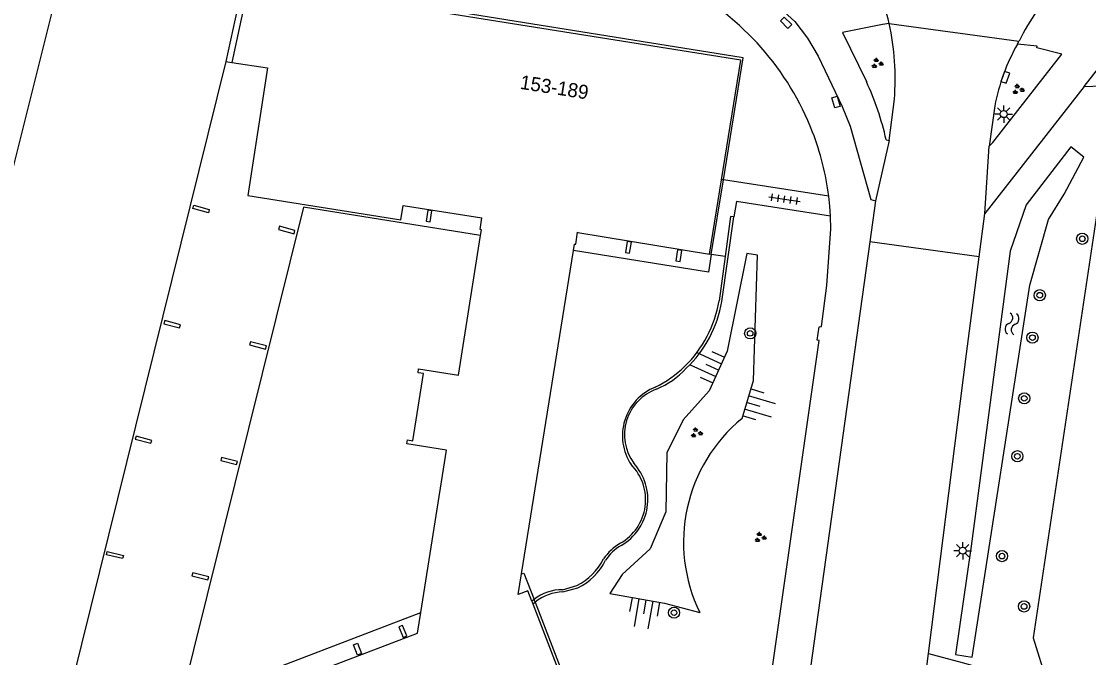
# Model space of a CAD drawing. Extents: x 131000 to 133013, y 393000 to 396501.
# Drawn here: x 131578.2 to 131654.4, y 394722.3 to 394767.7 of the extents above; entities that cross this region are included whole.
import ezdxf

# ---------------------------------------------------------------- set-up
doc = ezdxf.new("R2010")
doc.units = 0
for name, color, linetype in [('gg-afsc-hekwerk', 7, 'Continuous'), ('gg-afsc-muur', 7, 'Continuous'), ('gg-anno-huisnummerreeks BGT', 7, 'Continuous'), ('gg-bbg-hoofdgebouw', 7, 'Continuous'), ('gg-bbg-luifel en loopbrug', 7, 'Continuous'), ('gg-bbg-onder overbouw', 7, 'Continuous'), ('gg-bbg-pand overbouw', 7, 'Continuous'), ('gg-bbg-pilaar onder overbouw', 7, 'Continuous'), ('gg-knt-BGT kruinlijn', 7, 'Continuous'), ('gg-knt-verharding', 7, 'Continuous'), ('gg-knt-verharding nz', 7, 'Continuous'), ('gg-kntw-greppel-droge sloot', 7, 'Continuous'), ('gt-grn-groengrens', 7, 'Continuous'), ('gt-grn-vlakafsluiter', 7, 'Continuous'), ('gt-grn-weggrens', 7, 'Continuous'), ('gt-symb-boom', 7, 'Continuous'), ('gt-symb-groenvak', 7, 'Continuous'), ('gt-symb-kolk', 7, 'Continuous'), ('gt-symb-kolk center center', 7, 'Continuous'), ('gt-symb-lichtmast', 7, 'Continuous'), ('gt-symb-talud symbool', 7, 'Continuous'), ('gt-symb-tegel verharding', 7, 'Continuous'), ('gt-symb-watersymbool', 7, 'Continuous')]:
    doc.layers.add(name, color=color, linetype=linetype)

# ---------------------------------------------------------------- blocks, each defined once
blk = doc.blocks.new('gt0-BOOM')
at = {"layer": 'gt-symb-boom'}
for radius in [0.4, 0.2]:
    blk.add_circle((0, 0), radius, dxfattribs=at)
blk = doc.blocks.new('gt0-KOLK')
at = {"layer": 'gt-symb-kolk'}
blk.add_lwpolyline([(0, 0), (0.375, 0), (0.375, 0.4), (-0.375, 0.4), (-0.375, 0), (0, 0)], dxfattribs=at)
blk = doc.blocks.new('gt0-LMAST')
at = {"layer": 'gt-symb-lichtmast'}
for p, q in [((-0.182, 0.173), (-0.447, 0.438)), ((-0.005, 0.246), (-0.005, 0.621)), ((0.172, 0.173), (0.437, 0.438)), ((-0.255, -0.004), (-0.63, -0.004)), ((-0.182, -0.181), (-0.447, -0.446)), ((-0.005, -0.254), (-0.005, -0.629)), ((0.437, -0.446), (0.172, -0.181)), ((0.245, -0.004), (0.62, -0.004))]:
    blk.add_line(p, q, dxfattribs=at)
blk.add_circle((-0.005, -0.004), 0.25, dxfattribs=at)
blk = doc.blocks.new('gt0-WA')
at = {"layer": 'gt-symb-watersymbool'}
for centre, start, end in [((-0.323, 0.022), 28.07249, 151.92751), ((0.427, 0.422), 208.07248, 331.92751), ((-0.323, -0.428), 28.07249, 151.92751), ((0.427, -0.028), 208.07248, 331.92751)]:
    blk.add_arc(centre, 0.425, start, end, dxfattribs=at)
blk = doc.blocks.new('gt0-GRVAK')
at = {"layer": 'gt-symb-groenvak'}
for p, q in [((-0.11, 0.189), (-0.228, 0.24)), ((-0.182, 0.153), (0.088, 0.153)), ((-0.091, 0.211), (-0.156, 0.322)), ((-0.047, 0.214), (-0.047, 0.393)), ((-0.004, 0.211), (0.061, 0.322)), ((0.015, 0.189), (0.133, 0.24)), ((0.262, -0.052), (0.197, 0.059)), ((0.305, -0.049), (0.305, 0.13)), ((0.349, -0.052), (0.414, 0.059)), ((-0.245, -0.228), (-0.363, -0.177)), ((-0.318, -0.264), (-0.047, -0.264)), ((-0.226, -0.206), (-0.291, -0.095)), ((-0.183, -0.203), (-0.183, -0.024)), ((-0.139, -0.206), (-0.074, -0.095)), ((-0.12, -0.228), (-0.002, -0.177)), ((0.243, -0.074), (0.125, -0.023)), ((0.17, -0.11), (0.441, -0.11)), ((0.368, -0.074), (0.486, -0.023))]:
    blk.add_line(p, q, dxfattribs=at)
blk = doc.blocks.new('gt0-TEG1')
at = {"layer": 'gt-symb-tegel verharding'}
for p, q in [((-1.125, 0), (1.125, 0)), ((-0.9, -0.25), (-0.9, 0.25)), ((-0.45, -0.25), (-0.45, 0.25)), ((0, -0.25), (0, 0.25)), ((0.45, -0.25), (0.45, 0.25)), ((0.9, -0.25), (0.9, 0.25))]:
    blk.add_line(p, q, dxfattribs=at)
blk = doc.blocks.new('gt0-KOLKCC')
at = {"layer": 'gt-symb-kolk center center'}
blk.add_lwpolyline([(-0.375, 0.2), (0.375, 0.2), (0.375, -0.2), (-0.375, -0.2)], close=True, dxfattribs=at)
blk = doc.blocks.new('gt0-TALUD_1')
at = {"layer": 'gt-symb-talud symbool'}
for p, q in [((-1, -1), (-1, 0)), ((-0.5, -2), (-0.5, 0)), ((0, -1), (0, 0)), ((0.5, -2), (0.5, 0)), ((1, -1), (1, 0))]:
    blk.add_line(p, q, dxfattribs=at)

msp = doc.modelspace()

# ---------------------------------------------------------------- linework, layer by layer
at = {"layer": 'gg-afsc-hekwerk'}
for p, q in [((131655.694, 394758.916), (131650.419, 394723.693)), ((131650.419, 394723.693), (131652.447, 394717.205))]:
    msp.add_line(p, q, dxfattribs=at)
at = {"layer": 'gg-afsc-muur'}
for p, q in [((131628.193, 394747.714), (131629.065, 394753.745)), ((131628.431, 394750.927), (131627.996, 394747.749)), ((131616.833, 394727.134), (131617.849, 394727.444)), ((131616.861, 394726.996), (131617.921, 394727.27)), ((131614.797, 394726.447), (131614.643, 394726.318)), ((131614.717, 394726.125), (131614.872, 394726.252))]:
    msp.add_line(p, q, dxfattribs=at)
msp.add_lwpolyline([(131629.065, 394753.745), (131628.82, 394753.775), (131628.431, 394750.927)], dxfattribs=at)
for centre, radius, start, end in [((131619.554, 394749.182), 8.563, 314.58615, 350.36449), ((131619.77, 394749.127), 8.541, 313.57472, 350.47979), ((131619.41, 394749.578), 8.948, 296.80768, 313.46606), ((131621.13, 394747.123), 6.164, 292.93005, 317.2528), ((131624.837, 394738.129), 3.733, 111.89341, 213.60282), ((131624.705, 394738.196), 3.455, 109.84225, 216.09404), ((131619.201, 394733.555), 3.56, 299.50966, 44.79132), ((131619.119, 394733.585), 3.8, 299.95821, 42.67862), ((131623.097, 394726.925), 4.129, 121.24342, 144.28531), ((131622.622, 394727.463), 3.254, 119.55802, 146.91315), ((131616.073, 394731.118), 4.08, 295.79952, 334.1097), ((131616.049, 394731.122), 4.283, 295.91233, 333.91334), ((131616.791, 394723.899), 3.236, 89.25323, 128.03827), ((131617.075, 394723.393), 3.61, 93.40155, 127.61581)]:
    msp.add_arc(centre, radius, start, end, dxfattribs=at)
at = {"layer": 'gg-bbg-hoofdgebouw'}
for p, q in [((131594.6, 394771.102), (131593.227, 394764.773)), ((131613.902, 394728.259), (131617.613, 394751.342))]:
    msp.add_line(p, q, dxfattribs=at)
msp.add_lwpolyline([(131606.717, 394725.508), (131608.55, 394737.101), (131605.715, 394737.55), (131605.759, 394737.826), (131606.144, 394737.765), (131606.904, 394742.566), (131606.518, 394742.627), (131606.562, 394742.904), (131609.397, 394742.455), (131610.971, 394752.41)], dxfattribs=at)
at = {"layer": 'gg-bbg-luifel en loopbrug'}
msp.add_line((131567.175, 394715.452), (131581.322, 394772.031), dxfattribs=at)
at = {"layer": 'gg-bbg-onder overbouw'}
for p, q in [((131627.314, 394751.08), (131628.171, 394756.401)), ((131613.666, 394726.791), (131613.902, 394728.259)), ((131614.643, 394726.318), (131614.717, 394726.125)), ((131606.486, 394724.046), (131606.717, 394725.508))]:
    msp.add_line(p, q, dxfattribs=at)
for points in [[(131628.171, 394756.401), (131629.547, 394764.937), (131604.297, 394768.953)], [(131593.227, 394764.773), (131595.779, 394764.372), (131594.362, 394755.262), (131605.287, 394753.534), (131605.449, 394754.561), (131611.08, 394753.676)], [(131610.971, 394752.41), (131611.036, 394752.822), (131610.947, 394752.836), (131611.08, 394753.676)], [(131617.613, 394751.342), (131617.687, 394751.803), (131617.77, 394751.79), (131617.905, 394752.661)], [(131617.905, 394752.661), (131617.931, 394752.625), (131627.314, 394751.08)], [(131614.643, 394726.318), (131614.359, 394727.057), (131613.666, 394726.791)], [(131614.717, 394726.125), (131619.39, 394713.959), (131612.005, 394711.133)], [(131579.001, 394709.353), (131586.329, 394707.557), (131583.018, 394716.219), (131593.433, 394720.2), (131593.815, 394719.201), (131606.486, 394724.046)]]:
    msp.add_lwpolyline(points, dxfattribs=at)
at = {"layer": 'gg-bbg-pand overbouw'}
for p, q in [((131592.808, 394764.839), (131593.227, 394764.773)), ((131627.444, 394751.062), (131628.305, 394756.38)), ((131614.872, 394726.252), (131614.797, 394726.447))]:
    msp.add_line(p, q, dxfattribs=at)
for points in [[(131628.305, 394756.38), (131629.716, 394765.1), (131604.326, 394769.158)], [(131592.808, 394764.839), (131580.567, 394715.465), (131579.001, 394709.353)], [(131610.971, 394752.41), (131598.354, 394754.438), (131589.513, 394718.92), (131606.717, 394725.508)], [(131627.444, 394751.062), (131627.239, 394749.795), (131617.613, 394751.342)], [(131613.902, 394728.259), (131614.075, 394728.325), (131614.797, 394726.447)], [(131614.872, 394726.252), (131619.632, 394713.876), (131612.892, 394711.268), (131612.076, 394710.956)]]:
    msp.add_lwpolyline(points, dxfattribs=at)
at = {"layer": 'gg-bbg-pilaar onder overbouw'}
for points in [[(131590.447, 394754.339), (131590.512, 394754.58), (131591.621, 394754.284), (131591.557, 394754.043), (131590.447, 394754.339)], [(131607.093, 394753.439), (131607.389, 394753.392), (131607.513, 394754.172), (131607.217, 394754.219), (131607.093, 394753.439)], [(131596.63, 394753.08), (131596.566, 394752.839), (131597.675, 394752.543), (131597.739, 394752.784), (131596.63, 394753.08)], [(131621.32, 394751.207), (131621.617, 394751.16), (131621.74, 394751.94), (131621.443, 394751.987), (131621.32, 394751.207)], [(131624.92, 394750.61), (131625.216, 394750.563), (131625.34, 394751.343), (131625.044, 394751.39), (131624.92, 394750.61)], [(131588.448, 394746.34), (131588.39, 394746.122), (131589.501, 394745.816), (131589.561, 394746.033), (131588.448, 394746.34)], [(131594.563, 394744.837), (131594.5, 394744.602), (131595.635, 394744.315), (131595.695, 394744.55), (131594.563, 394744.837)], [(131586.397, 394738.094), (131586.341, 394737.884), (131587.457, 394737.586), (131587.513, 394737.796), (131586.397, 394738.094)], [(131592.504, 394736.585), (131592.446, 394736.365), (131593.575, 394736.07), (131593.632, 394736.29), (131592.504, 394736.585)], [(131585.49, 394729.575), (131585.438, 394729.359), (131584.288, 394729.637), (131584.34, 394729.854), (131585.49, 394729.575)], [(131590.44, 394728.338), (131590.389, 394728.122), (131591.527, 394727.851), (131591.579, 394728.068), (131590.44, 394728.338)], [(131605.404, 394724.594), (131605.137, 394724.495), (131605.454, 394723.737), (131605.721, 394723.836), (131605.404, 394724.594)], [(131601.918, 394723.21), (131602.198, 394723.317), (131602.48, 394722.579), (131602.2, 394722.472), (131601.918, 394723.21)]]:
    msp.add_lwpolyline(points, dxfattribs=at)
at = {"layer": 'gg-knt-BGT kruinlijn'}
msp.add_lwpolyline([(131629.639, 394739.366), (131630.451, 394742.067), (131630.746, 394751.005), (131629.992, 394751.139), (131628.588, 394744.166), (131627.295, 394741.326), (131625.434, 394739.273), (131624.268, 394736.9), (131624.213, 394732.69), (131623.085, 394730.049), (131621.085, 394728.224), (131620.202, 394726.872), (131624.103, 394726.187), (131626.621, 394725.509)], dxfattribs=at)
msp.add_arc((131636.925, 394730.522), 11.458, 129.4818, 205.94437, dxfattribs=at)
at = {"layer": 'gg-knt-verharding'}
for p, q in [((131594.151, 394771.028), (131592.808, 394764.839)), ((131640.141, 394767.546), (131639.664, 394767.485)), ((131649.298, 394766.083), (131649.403, 394766.297)), ((131654.064, 394763.061), (131646.963, 394753.983)), ((131640.129, 394759.191), (131640.51, 394762.14)), ((131647.674, 394761.662), (131647.276, 394758.798)), ((131640.129, 394759.191), (131639.155, 394754.893)), ((131639.926, 394759.244), (131640.129, 394759.191)), ((131646.963, 394753.983), (131647.276, 394758.798)), ((131628.305, 394756.38), (131628.171, 394756.401)), ((131635.827, 394755.223), (131628.305, 394756.38)), ((131639.155, 394754.893), (131638.75, 394751.972)), ((131646.556, 394750.889), (131646.963, 394753.983)), ((131638.75, 394751.972), (131630.84, 394694.98)), ((131645.645, 394743.974), (131646.556, 394750.889)), ((131642.939, 394722.588), (131645.645, 394743.974))]:
    msp.add_line(p, q, dxfattribs=at)
for points in [[(131629.697, 394771.072), (131633.403, 394767.687), (131634.302, 394766.496), (131635.074, 394765.214), (131636.789, 394761.627), (131637.358, 394760.223), (131638.837, 394754.98), (131639.155, 394754.893)], [(131639.664, 394767.485), (131636.806, 394766.898), (131638.513, 394763.405)], [(131647.276, 394758.798), (131647.528, 394759.06), (131652.469, 394765.362), (131650.683, 394765.813), (131650.706, 394765.939), (131649.298, 394766.083)], [(131654.064, 394763.061), (131691.777, 394764.495), (131704.176, 394765.281)], [(131635.954, 394753.808), (131629.24, 394754.843), (131629.065, 394753.745)], [(131635.954, 394753.808), (131635.903, 394754.518), (131635.827, 394755.223)], [(131630.898, 394715.278), (131635.149, 394744.926), (131635, 394744.949), (131635.133, 394745.892), (131635.309, 394745.919), (131635.684, 394748.842), (131635.982, 394752.893), (131635.954, 394753.808)], [(131639.519, 394697.805), (131642.25, 394717.14), (131642.939, 394722.588)]]:
    msp.add_lwpolyline(points, dxfattribs=at)
for centre, radius, start, end in [((131616.219, 394752.793), 19.713, 41.41309, 61.89041), ((131625.276, 394763.838), 15.321, 14.00657, 24.06411), ((131663.928, 394759.02), 16.246, 144.55917, 153.38759), ((131622.018, 394763.593), 18.549, 355.50621, 12.30341), ((131661.827, 394758.972), 14.407, 150.42215, 169.23747), ((131616.083, 394752.614), 19.934, 21.13942, 41.53967), ((131619.582, 394754.656), 20.855, 12.70897, 24.80414), ((131616.296, 394752.745), 19.687, 7.22984, 21.00742)]:
    msp.add_arc(centre, radius, start, end, dxfattribs=at)
at = {"layer": 'gg-knt-verharding nz'}
msp.add_line((131640.141, 394767.546), (131649.403, 394766.297), dxfattribs=at)
msp.add_lwpolyline([(131654.064, 394763.061), (131655.428, 394764.813), (131691.855, 394766.19), (131704.435, 394766.987)], dxfattribs=at)
at = {"layer": 'gg-kntw-greppel-droge sloot'}
msp.add_lwpolyline([(131651.504, 394753.559), (131652.626, 394755.378), (131654.024, 394757.996), (131653.09, 394758.755), (131649.923, 394754.605), (131648.782, 394751.3), (131645.981, 394730.239), (131644.869, 394722.521), (131646.059, 394722.315), (131650.169, 394748.866), (131651.504, 394753.559)], dxfattribs=at)
at = {"layer": 'gt-grn-groengrens'}
msp.add_lwpolyline([(131642.939, 394722.588), (131645.349, 394721.948), (131647.452, 394721.348), (131648.237, 394721.053), (131649.415, 394720.366), (131650.2, 394719.875), (131650.886, 394719.286), (131652.447, 394717.205)], dxfattribs=at)
at = {"layer": 'gt-grn-vlakafsluiter'}
for p, q in [((131627.444, 394751.062), (131627.314, 394751.08)), ((131628.431, 394750.927), (131627.444, 394751.062))]:
    msp.add_line(p, q, dxfattribs=at)
at = {"layer": 'gt-grn-weggrens'}
msp.add_line((131646.556, 394750.889), (131638.75, 394751.972), dxfattribs=at)

# ---------------------------------------------------------------- block references
at = {"layer": 'gt-symb-boom'}
for p in [(131653.917, 394752.184), (131650.887, 394748.153), (131630.221, 394745.431), (131650.363, 394745.129), (131649.775, 394740.796), (131649.288, 394736.662), (131648.19, 394729.534), (131649.766, 394725.945), (131624.787, 394725.499)]:
    msp.add_blockref('gt0-BOOM', p, dxfattribs=at)
at = {"layer": 'gt-symb-groenvak'}
for p in [(131639.273, 394764.695), (131649.329, 394762.837), (131626.377, 394738.328), (131630.929, 394730.867)]:
    msp.add_blockref('gt0-GRVAK', p, dxfattribs=at)
at = {"layer": 'gt-symb-kolk', "rotation": -109.44956876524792}
msp.add_blockref('gt0-KOLK', (131648.243, 394763.77), dxfattribs=at)
at = {"layer": 'gt-symb-kolk center center'}
for p, rotation in [((131632.781, 394767.604), -44.756879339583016), ((131636.341, 394761.937), 105.66210634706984)]:
    msp.add_blockref('gt0-KOLKCC', p, dxfattribs=dict(at, rotation=rotation))
at = {"layer": 'gt-symb-lichtmast'}
for p in [(131648.318, 394761.084), (131645.392, 394729.921)]:
    msp.add_blockref('gt0-LMAST', p, dxfattribs=at)
at = {"layer": 'gt-symb-talud symbool'}
for p, xscale, yscale, rotation in [((131627.974, 394742.812), 0.9997479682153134, 0.9997479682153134, -114.4629268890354), ((131629.965, 394740.506), 1.0003539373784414, 1.0003539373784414, 73.26783977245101), ((131622.796, 394726.396), 1.000076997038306, 1.000076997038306, -9.961516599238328)]:
    msp.add_blockref('gt0-TALUD_1', p, dxfattribs=dict(at, xscale=xscale, yscale=yscale, rotation=rotation))
at = {"layer": 'gt-symb-tegel verharding', "rotation": -8.27589282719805}
msp.add_blockref('gt0-TEG1', (131632.667, 394755.01), dxfattribs=at)
at = {"layer": 'gt-symb-watersymbool', "rotation": -97.5870690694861}
msp.add_blockref('gt0-WA', (131648.914, 394746.161), dxfattribs=at)

# ---------------------------------------------------------------- texts
at = {"layer": 'gg-anno-huisnummerreeks BGT'}
msp.add_text('153-189', height=1, rotation=351, dxfattribs=at).set_placement((131613.749, 394762.891))

doc.saveas('drawing.dxf')
